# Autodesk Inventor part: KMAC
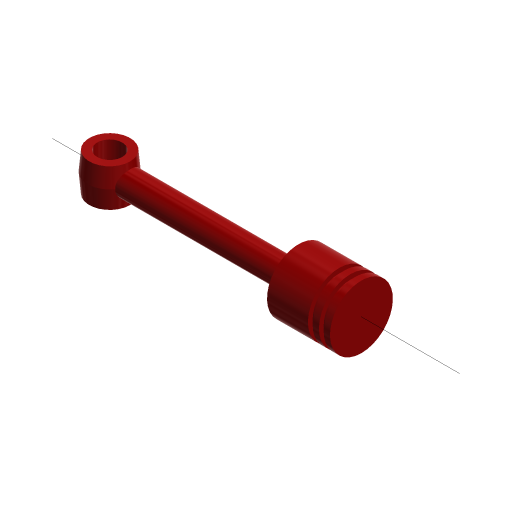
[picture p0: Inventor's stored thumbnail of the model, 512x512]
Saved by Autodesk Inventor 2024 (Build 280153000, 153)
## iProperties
Company: ATC
Shininess: 20.0
Angle Display Precision: 2
Document Length Units: 11269
Document Angle Units: 11279
Document Time Units: 11290
Document Mass Units: 11283
Document Length Units Precision: 3
Document Angle Units Precision: 2
Created: 2023-03
Part Number: KMAC
Material: Stal węglowa
Document SubType Name: Modelowanie
Designer: Andrzej Jaskulski
Density: 7.87 g/cm^3
Stock Number: Dźwignia kątowa
Mass: 346.136 g
Surface Area: 128.086 cm^2
Volume: 34.6136 cm^3
Appearance: Czerwona
Checked By: A.J.
Engr Approved By: Andrzej Jaskulski
Mfg Approved By: Andrzej Jaskulski
Authority: A.J.
Density: 0.0
Volumn: 0.0
Area: 0.0
PropertySet Name: Model Information
Control State: 0
Master: False
Checked Out: False
Title: A.J.: Kurs R2024-MEP
Author: Andrzej Jaskulski
Revision Number: 1/24
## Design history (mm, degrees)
node "Początek"
  node "Płaszczyzna YZ"
  node "Płaszczyzna XZ"
  node "Płaszczyzna XY"
  node "Oś X"
  node "Oś Y"
  node "Oś Z"
sketch "Szkic1"
  geometry: C1 r 7 at (0, 0); C2 r 4 at (0, 0)
  constraints: 2 centre point, 1 coincident, 1 other
  dimensions: "d11" = 14 diameter of C1; "d12" = 8 diameter of C2
extrude "Wyciągnięcie proste1" new body sketch "Szkic1" stored distance "d16" = 12; taper "d17" = -5 deg
sketch "Szkic2"
  geometry: C1 r 4 at (0, 0)
  constraints: 1 centre point
  dimensions: "d23" = 8 diameter of C1
extrude "Wyciągnięcie proste4" join sketch "Szkic2" distance "d24" = 60; taper "d25" = 0 deg
extrude "Wyciągnięcie proste5" cut sketch "Szkic1" extent not by distance; stored distance "d26" = 100; taper "d27" = 0 deg
node "Oś konstrukcyjna1"
sketch "Szkic3"
  geometry: C1 r 10 at (0, 0); 1 further point
  constraints: 1 centre point, 1 coincident
  dimensions: "d37" = 20 diameter of C1
extrude "Wyciągnięcie proste6" join sketch "Szkic3" distance "d28" = 20; taper "d29" = 0 deg
revolve "Obrót1" stored, may be unused: angle "d36" = 90 deg
node "Bryła1"
node "Korpusy bryłowe"
node "Korpusy powierzchniowe"
node "Punkt środkowy"
sketch "Szkic4"
  geometry: L1 (-60, 10)-(-80, 10) reference; L2 (-78, 10)-(-78, 8.5); L3 (-78, 8.5)-(-76.5, 8.5); L4 (-76.5, 8.5)-(-76.5, 10); L5 (-74.5, 10)-(-74.5, 8.5); L6 (-74.5, 8.5)-(-73, 8.5); L7 (-73, 8.5)-(-73, 10); L8 (24.4, 0)-(-97.4, 0) reference
  constraints: 12 end point, 4 perpendicular, 4 point on line, 2 equal length, 2 parallel
  dimensions: "d32" = 2 distance from line of L2 L1.end; "d33" = 1.5 distance of L2.end L3.end; "d34" = 2 distance between parallel lines of L5 L4; "d35" = 1.5 distance of L2.start L2.end
